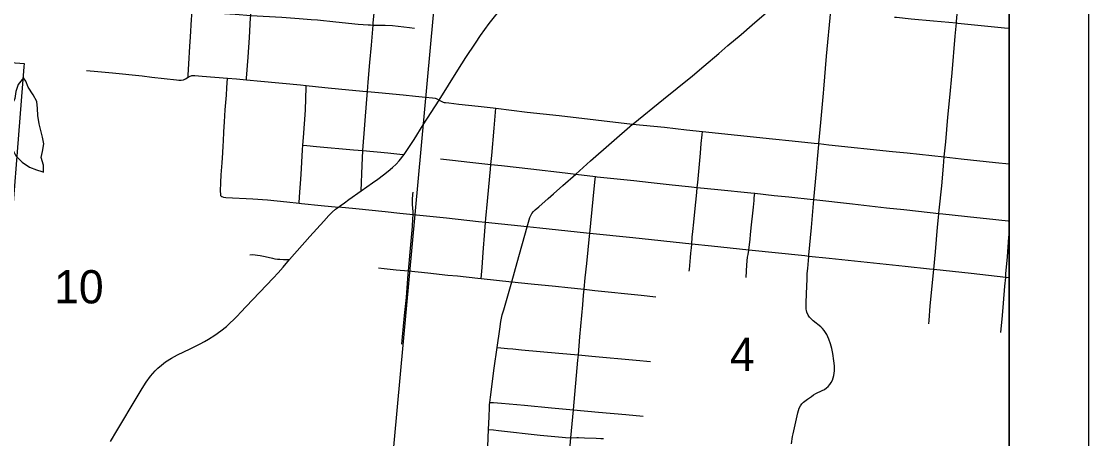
# Model space of a CAD drawing. Extents: x 0 to 34, y 0 to 22.
# Drawn here: x 7.657 to 9, y 17.42 to 17.945 of the extents above; entities that cross this region are included whole.
import ezdxf

# ---------------------------------------------------------------- set-up
doc = ezdxf.new("R2010")
doc.units = 0
for name, color, linetype in [('Default', 7, 'Continuous'), ('GM_X_City_Street', 7, 'Continuous'), ('GM_X_County_Road', 7, 'Continuous'), ('GM_X_Minor_Lake', 7, 'Continuous'), ('GM_X_Section', 7, 'Continuous'), ('GM_X_Section_Text', 7, 'Continuous'), ('SC_Shading1', 7, 'Continuous'), ('SH_Data', 7, 'Continuous')]:
    doc.layers.add(name, color=color, linetype=linetype)

msp = doc.modelspace()

# ---------------------------------------------------------------- linework, layer by layer
at = {"layer": 'Default'}
msp.add_lwpolyline([(8.9, 17.0075), (8.9, 18.003), (8.1859, 18.0729), (8.0956, 17.09)], close=True, dxfattribs=at)
at = {"layer": 'GM_X_City_Street'}
for points in [[(8.9, 14.1), (8.9, 20.0308)], [(7.9399, 17.8717), (7.94, 17.8737), (7.9422, 17.9003), (7.9437, 17.925), (7.9453, 17.9496), (7.9455, 17.9529), (7.9463, 17.9676), (7.9474, 17.9863), (7.9479, 17.9951), (7.9484, 18.0012), (7.9488, 18.0073), (7.9494, 18.0163), (7.9498, 18.0221), (7.9505, 18.0321), (7.9516, 18.053), (7.9533, 18.0748), (7.9542, 18.0895), (7.9544, 18.0932)], [(8.0844, 17.732), (8.0855, 17.7637), (8.0864, 17.7827), (8.0917, 17.8472), (8.0924, 17.8572), (8.0933, 17.8688), (8.0952, 17.8936), (8.0974, 17.9152), (8.0996, 17.9407), (8.0997, 17.943), (8.1025, 17.9737), (8.1051, 18.0015), (8.1059, 18.0121), (8.1062, 18.0159), (8.1071, 18.0264), (8.1089, 18.0477), (8.1101, 18.0632), (8.1113, 18.078), (8.1117, 18.0831)], [(7.8666, 17.8749), (7.8667, 17.8778), (7.8674, 17.892), (7.8688, 17.9137), (7.8696, 17.926), (7.871, 17.9477), (7.8717, 17.9577), (7.8733, 17.9814), (7.8749, 18.0028), (7.8763, 18.0268)], [(8.7987, 17.5644), (8.7992, 17.5686), (8.8007, 17.5872), (8.8051, 17.6328), (8.8073, 17.6552), (8.8099, 17.6862), (8.8111, 17.6983), (8.8115, 17.7036), (8.8119, 17.7075), (8.8152, 17.7381), (8.8174, 17.7629), (8.8183, 17.7746), (8.8201, 17.7938), (8.8229, 17.8247), (8.8254, 17.8494), (8.8281, 17.8804), (8.8322, 17.9268), (8.8335, 17.9433), (8.8336, 17.9453), (8.8366, 17.9784), (8.8384, 17.9979), (8.841, 18.0283), (8.8412, 18.0304)], [(7.8717, 17.9577), (7.8761, 17.9573), (7.8918, 17.9563), (7.9258, 17.9544), (7.9455, 17.9529), (7.9844, 17.9505), (8.0063, 17.9489), (8.0215, 17.9477), (8.0293, 17.9471), (8.0527, 17.9449), (8.0805, 17.942), (8.0934, 17.941), (8.0963, 17.9409), (8.0996, 17.9407), (8.1052, 17.9407), (8.1146, 17.9406), (8.1238, 17.94), (8.1454, 17.9375), (8.1517, 17.9367)], [(8.2431, 17.3884), (8.2447, 17.4317), (8.2453, 17.4473), (8.2458, 17.4592), (8.246, 17.4627), (8.2463, 17.4656), (8.2472, 17.4721), (8.2519, 17.5086), (8.2557, 17.5347), (8.259, 17.5578), (8.2604, 17.5676), (8.2611, 17.5716), (8.262, 17.5757), (8.2638, 17.582), (8.2691, 17.5998), (8.274, 17.6176), (8.2807, 17.6416), (8.2932, 17.6866), (8.294, 17.6895), (8.2967, 17.6983), (8.2979, 17.7011), (8.2994, 17.7036), (8.3012, 17.706), (8.3035, 17.708), (8.308, 17.7118), (8.3197, 17.7223), (8.3266, 17.7283), (8.3384, 17.7387), (8.3546, 17.7531), (8.3732, 17.7696), (8.4261, 17.816), (8.4268, 17.8165), (8.4651, 17.8475), (8.4822, 17.8613), (8.5013, 17.8768), (8.5156, 17.8889), (8.5345, 17.9048), (8.546, 17.915), (8.5625, 17.929), (8.5767, 17.941), (8.5976, 17.9589)], [(8.647, 17.5755), (8.6454, 17.5794), (8.6449, 17.5812), (8.6446, 17.5831), (8.6443, 17.5853), (8.6443, 17.5881), (8.6451, 17.6052), (8.6453, 17.6091), (8.6454, 17.6133), (8.6456, 17.6197), (8.6458, 17.6237), (8.6459, 17.6279), (8.6464, 17.6341), (8.6479, 17.6495), (8.648, 17.6512), (8.6511, 17.6858), (8.6542, 17.721), (8.6574, 17.7566), (8.6588, 17.772), (8.6604, 17.7904), (8.6605, 17.7915), (8.6628, 17.8182), (8.6662, 17.8551), (8.6666, 17.8599), (8.6702, 17.9014), (8.6754, 17.9586)], [(7.7387, 17.8837), (7.753, 17.8824), (7.7716, 17.8807), (7.8086, 17.8767), (7.821, 17.875), (7.8518, 17.8716), (7.8548, 17.8714), (7.8578, 17.8714), (7.8607, 17.8717), (7.8633, 17.8728), (7.8666, 17.8749), (7.8683, 17.876), (7.8712, 17.877), (7.8749, 17.8771), (7.8841, 17.8762), (7.9161, 17.8737), (7.9275, 17.8728), (7.9399, 17.8717), (7.9582, 17.87), (8.0079, 17.8656), (8.0153, 17.8648), (8.0385, 17.8622), (8.0601, 17.8599), (8.091, 17.8572), (8.0924, 17.8572), (8.1064, 17.856), (8.1372, 17.8528), (8.1526, 17.8513), (8.1653, 17.8501), (8.1741, 17.8491), (8.1774, 17.8486), (8.1786, 17.8482), (8.1796, 17.8478), (8.1824, 17.8463), (8.1853, 17.8447), (8.1867, 17.8441), (8.1876, 17.8438), (8.189, 17.8433), (8.1905, 17.8431), (8.1949, 17.8426), (8.2073, 17.8413), (8.2318, 17.8385), (8.2504, 17.8364), (8.2539, 17.836), (8.2935, 17.8312), (8.3336, 17.8267), (8.4261, 17.816), (8.4663, 17.812), (8.494, 17.8089), (8.5139, 17.8068), (8.602, 17.7976), (8.6267, 17.7949), (8.6545, 17.7921), (8.6605, 17.7915), (8.673, 17.7901), (8.7531, 17.7815), (8.7714, 17.7797), (8.8027, 17.7763), (8.8183, 17.7746), (8.8396, 17.7724), (8.8827, 17.7678), (8.9, 17.7661)], [(7.9078, 17.7259), (7.9076, 17.7277), (7.9073, 17.7316), (7.9079, 17.7427), (7.9084, 17.752), (7.9096, 17.7673), (7.9103, 17.7798), (7.9107, 17.7885), (7.911, 17.7945), (7.9117, 17.8064), (7.9123, 17.8187), (7.9134, 17.8341), (7.9149, 17.8526), (7.9155, 17.8618), (7.9161, 17.8737)], [(8.0065, 17.7164), (8.007, 17.7243), (8.0088, 17.7524), (8.0107, 17.7835), (8.0112, 17.7894), (8.0119, 17.7991), (8.0142, 17.8334), (8.0152, 17.8625), (8.0153, 17.8648)], [(8.2355, 17.6217), (8.2358, 17.6261), (8.2365, 17.6354), (8.2379, 17.6542), (8.2399, 17.6812), (8.2408, 17.6921), (8.2413, 17.6972), (8.2433, 17.7191), (8.245, 17.7371), (8.2471, 17.7592), (8.2477, 17.7653), (8.2487, 17.7766), (8.2518, 17.8107), (8.2534, 17.831), (8.2539, 17.836)], [(8.4973, 17.631), (8.4975, 17.6331), (8.498, 17.6381), (8.4985, 17.6431), (8.4989, 17.6479), (8.4995, 17.6536), (8.5001, 17.6601), (8.5006, 17.6648), (8.501, 17.6736), (8.5017, 17.6807), (8.503, 17.6927), (8.5043, 17.7054), (8.5068, 17.7301), (8.5074, 17.7363), (8.508, 17.7424), (8.5114, 17.7796), (8.5125, 17.7914), (8.5136, 17.8026), (8.5139, 17.8068)], [(8.0112, 17.7894), (8.0161, 17.789), (8.0284, 17.7879), (8.0747, 17.7838), (8.0864, 17.7827), (8.1178, 17.7797), (8.1329, 17.7782), (8.1385, 17.7777)], [(8.1843, 17.7722), (8.1995, 17.7707), (8.221, 17.7682), (8.2477, 17.7653), (8.2611, 17.7638), (8.2981, 17.7597), (8.3413, 17.7548), (8.3546, 17.7531), (8.3794, 17.75), (8.3814, 17.7497), (8.4277, 17.7449), (8.4492, 17.7424), (8.4643, 17.7409), (8.4759, 17.7397), (8.4964, 17.7375), (8.5074, 17.7363), (8.5333, 17.7336), (8.5747, 17.7295), (8.5798, 17.7289), (8.6041, 17.7263), (8.6226, 17.7244), (8.6534, 17.7211), (8.6542, 17.721), (8.7026, 17.7155), (8.7457, 17.7107), (8.7672, 17.7085), (8.7857, 17.7066), (8.8115, 17.7036), (8.8164, 17.7031), (8.8594, 17.6984), (8.8715, 17.6972), (8.8989, 17.6943), (8.9, 17.6942)], [(8.3362, 17.2631), (8.3366, 17.2688), (8.3383, 17.2936), (8.3408, 17.3274), (8.3427, 17.3526), (8.3474, 17.4116), (8.3482, 17.4212), (8.3515, 17.4564), (8.3573, 17.519), (8.3578, 17.5255), (8.3598, 17.5482), (8.3632, 17.5885), (8.3644, 17.6008), (8.3651, 17.6081), (8.3665, 17.6223), (8.3683, 17.6405), (8.3718, 17.6749), (8.3721, 17.6782), (8.3764, 17.7214), (8.3786, 17.743), (8.3794, 17.75)], [(7.9078, 17.7259), (7.9092, 17.7249), (7.9111, 17.7241), (7.9142, 17.7236), (7.9479, 17.7221), (7.9664, 17.7207), (7.991, 17.7182), (8.0065, 17.7164), (8.0095, 17.7161), (8.0342, 17.7136), (8.0558, 17.7116)], [(8.1354, 17.5391), (8.1364, 17.5483), (8.1391, 17.575), (8.1413, 17.5977), (8.1437, 17.6276), (8.144, 17.6311), (8.1473, 17.6686), (8.149, 17.6869), (8.1496, 17.6966), (8.1498, 17.7018), (8.1499, 17.7056), (8.1492, 17.7149), (8.1491, 17.721), (8.1495, 17.7272), (8.1499, 17.7303)], [(8.5691, 17.6228), (8.5698, 17.639), (8.5708, 17.6487), (8.5713, 17.6519), (8.5722, 17.6573), (8.5739, 17.6712), (8.5746, 17.6772), (8.5758, 17.6891), (8.5773, 17.7039), (8.578, 17.7114), (8.5789, 17.72), (8.5792, 17.7231), (8.5798, 17.7289)], [(8.8893, 17.5536), (8.8915, 17.5751), (8.8928, 17.5905), (8.8947, 17.6121), (8.8956, 17.6231), (8.8959, 17.6275), (8.8978, 17.649), (8.8997, 17.6736), (8.9, 17.6769)], [(7.9445, 17.6515), (7.9477, 17.6517), (7.9509, 17.6516), (7.9541, 17.6512), (7.9572, 17.6507), (7.9635, 17.6492), (7.9728, 17.6471), (7.9759, 17.6466), (7.979, 17.6461), (7.982, 17.6458), (7.9865, 17.6454), (7.9901, 17.6454), (7.9942, 17.6454)], [(8.1064, 17.6349), (8.1135, 17.6342), (8.1286, 17.6326), (8.144, 17.6311), (8.1682, 17.6286), (8.1933, 17.626), (8.2055, 17.6248), (8.2311, 17.6221), (8.2355, 17.6217), (8.274, 17.6176), (8.2983, 17.615), (8.3292, 17.6119), (8.3446, 17.6103), (8.3651, 17.6081), (8.3784, 17.6066), (8.4369, 17.6005), (8.4553, 17.5984)], [(8.628, 17.4263), (8.6338, 17.4526), (8.6347, 17.4556), (8.6358, 17.4585), (8.6373, 17.4612), (8.6391, 17.4637), (8.6413, 17.4659), (8.6461, 17.4699), (8.651, 17.4733), (8.6537, 17.475), (8.6566, 17.4767), (8.6593, 17.4781), (8.662, 17.4794), (8.6648, 17.4806), (8.6676, 17.482), (8.6699, 17.4838), (8.6722, 17.4858), (8.6743, 17.4882), (8.676, 17.4907), (8.6775, 17.4935), (8.6786, 17.4964), (8.6794, 17.4994), (8.6798, 17.5025), (8.6801, 17.5056), (8.68, 17.5118), (8.6795, 17.518), (8.6781, 17.5273), (8.6768, 17.5334), (8.6751, 17.5394), (8.6731, 17.5453), (8.6705, 17.551), (8.669, 17.5537), (8.6672, 17.5562), (8.6651, 17.5586), (8.6629, 17.5607), (8.6531, 17.5685), (8.6508, 17.5707), (8.6487, 17.573), (8.647, 17.5755)], [(8.2557, 17.5347), (8.2603, 17.5342), (8.2685, 17.5335), (8.2753, 17.5329), (8.2862, 17.532), (8.3333, 17.5278), (8.3578, 17.5255), (8.3749, 17.524), (8.4305, 17.5189), (8.4485, 17.5173)], [(8.2463, 17.4656), (8.2511, 17.4654), (8.2612, 17.4645), (8.2898, 17.462), (8.3241, 17.4588), (8.3515, 17.4564), (8.3832, 17.4535), (8.4175, 17.4505), (8.4393, 17.4484)], [(8.2447, 17.4317), (8.251, 17.431), (8.2571, 17.4303), (8.3098, 17.4246), (8.3372, 17.4218), (8.3415, 17.4215), (8.3482, 17.4212), (8.3557, 17.4214), (8.358, 17.4213), (8.3653, 17.421), (8.3803, 17.4205), (8.3862, 17.4203), (8.3892, 17.4203)], [(8.626, 17.4133), (8.6274, 17.4226), (8.628, 17.4263)]]:
    msp.add_lwpolyline(points, dxfattribs=at)
at = {"layer": 'GM_X_County_Road'}
for p, q in [((8.2932, 17.6866), (8.2408, 17.6921)), ((8.9, 17.6226), (8.8956, 17.6231))]:
    msp.add_line(p, q, dxfattribs=at)
for points in [[(8.1824, 17.8463), (8.2062, 17.8838), (8.2161, 17.8998), (8.2281, 17.918), (8.2346, 17.9277), (8.2457, 17.9425), (8.254, 17.9532), (8.2753, 17.9782)], [(8.7558, 17.9508), (8.758, 17.9506), (8.7768, 17.9486), (8.8046, 17.9459), (8.8335, 17.9433)], [(8.8335, 17.9433), (8.8354, 17.9431), (8.894, 17.9373), (8.9, 17.9367)], [(8.1385, 17.7777), (8.1511, 17.7965), (8.1626, 17.8151), (8.1824, 17.8463)], [(8.0844, 17.732), (8.0987, 17.7421), (8.1053, 17.7468), (8.1125, 17.7521), (8.1182, 17.7567), (8.1237, 17.7614), (8.1286, 17.7656), (8.1322, 17.7696), (8.1385, 17.7777)], [(8.0558, 17.7116), (8.0581, 17.7133), (8.0635, 17.7171), (8.0689, 17.7209), (8.0844, 17.732)], [(7.9942, 17.6454), (8.0199, 17.6744), (8.0374, 17.6939), (8.0436, 17.7009), (8.048, 17.7051), (8.0523, 17.7089), (8.0558, 17.7116)], [(8.1498, 17.7018), (8.1331, 17.7035), (8.1146, 17.7054), (8.0776, 17.7092), (8.0558, 17.7116)], [(8.2408, 17.6921), (8.2319, 17.693), (8.1918, 17.6974), (8.1498, 17.7018)], [(8.3721, 17.6782), (8.3678, 17.6787), (8.3091, 17.685), (8.2932, 17.6866)], [(8.5006, 17.6648), (8.4264, 17.6727), (8.3721, 17.6782)], [(8.5722, 17.6573), (8.5252, 17.6622), (8.5006, 17.6648)], [(8.6479, 17.6495), (8.6426, 17.65), (8.5722, 17.6573)], [(7.933, 17.5793), (7.9397, 17.5863), (7.9738, 17.622), (7.9801, 17.6288), (7.9861, 17.6359), (7.9942, 17.6454)], [(8.8051, 17.6328), (8.7998, 17.6333), (8.7691, 17.6366), (8.6735, 17.6468), (8.6479, 17.6495)], [(8.8956, 17.6231), (8.8523, 17.6278), (8.8051, 17.6328)], [(7.7688, 17.4166), (7.777, 17.4297), (7.8023, 17.4726), (7.8088, 17.4833), (7.8138, 17.4912), (7.8194, 17.4985), (7.8253, 17.5055), (7.8285, 17.5087), (7.833, 17.5126), (7.8381, 17.5166), (7.8455, 17.5212), (7.8534, 17.5254), (7.869, 17.5333), (7.8817, 17.5396), (7.8871, 17.5424), (7.8924, 17.5452), (7.9004, 17.5503), (7.908, 17.5557), (7.915, 17.5614), (7.9284, 17.5744), (7.933, 17.5793)]]:
    msp.add_lwpolyline(points, dxfattribs=at)
at = {"layer": 'GM_X_Minor_Lake'}
for points in [[(7.6596, 17.8743), (7.6528, 17.866), (7.65, 17.8569), (7.6485, 17.8482), (7.6458, 17.8418), (7.6427, 17.8323), (7.6407, 17.8232), (7.641, 17.8137), (7.6436, 17.8038), (7.6443, 17.7932), (7.6457, 17.7845), (7.6498, 17.7761), (7.6577, 17.7681), (7.6671, 17.7616), (7.6758, 17.7585), (7.6824, 17.7564)], [(7.6824, 17.7564), (7.6845, 17.7557), (7.6845, 17.7645), (7.6816, 17.774), (7.6835, 17.7815), (7.6851, 17.791), (7.6833, 17.7994), (7.6811, 17.8081), (7.6792, 17.8165), (7.6774, 17.8267), (7.6771, 17.8355), (7.6761, 17.8446), (7.6716, 17.8529), (7.6652, 17.8625), (7.6623, 17.8701), (7.6596, 17.8743)]]:
    msp.add_lwpolyline(points, dxfattribs=at)
at = {"layer": 'GM_X_Section'}
msp.add_lwpolyline([(7.1751, 18.1682), (8.1859, 18.0729), (8.0956, 17.09), (7.0855, 17.1656)], close=True, dxfattribs=at)
at = {"layer": 'SC_Shading1'}
for points in [[(8.9, 15.7724), (8.9, 20.5265)], [(7.5364, 17.9017), (7.6603, 17.8922), (7.66, 17.888), (7.6386, 17.6152)]]:
    msp.add_lwpolyline(points, dxfattribs=at)
at = {"layer": 'SH_Data'}
for p, q in [((9, 21), (9, 14)), ((8.9, 20.9), (8.9, 14.1))]:
    msp.add_line(p, q, dxfattribs=at)

# ---------------------------------------------------------------- texts
at = {"layer": 'GM_X_Section_Text'}
for s, height, p in [('10', 0.04186, (7.698, 17.5903)), ('4', 0.0419, (8.5484, 17.5052))]:
    msp.add_text(s, height=height, rotation=0, dxfattribs=at).set_placement(p)

doc.saveas('drawing.dxf')
